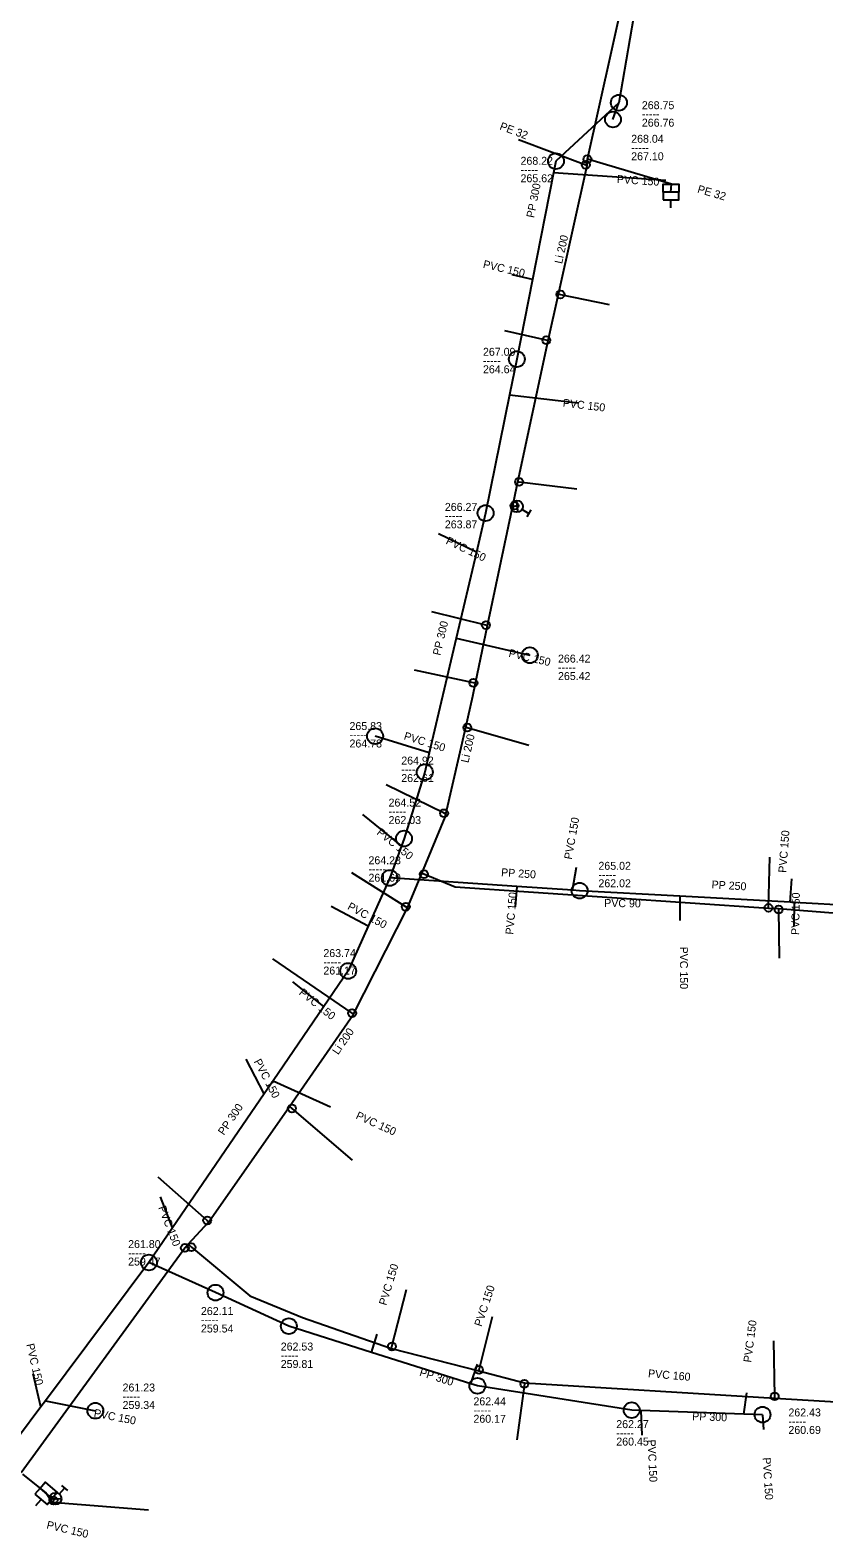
# Model space of a CAD drawing. Extents: x -770828 to -770111, y -1050344 to -1049447.
# Drawn here: x -770589.8 to -770489.8, y -1049915.1 to -1049725.3 of the extents above; entities that cross this region are included whole.
import ezdxf

# ---------------------------------------------------------------- set-up
doc = ezdxf.new("R2010")
doc.units = 0
doc.layers.add('Level 0', color=7, linetype='Continuous')

msp = doc.modelspace()

# ---------------------------------------------------------------- linework, layer by layer
at = {"layer": 'Level 0'}
for p, q in [((-770519.6, -1049741.56), (-770510.08, -1049699.01)), ((-770510.55, -1049704.66), (-770515.63, -1049734.44)), ((-770515.63, -1049734.44), (-770523.56, -1049741.79)), ((-770516.38, -1049736.55), (-770515.63, -1049734.44)), ((-770528.28, -1049739.05), (-770519.81, -1049742.26)), ((-770523.56, -1049741.79), (-770523.85, -1049743.26)), ((-770519.61, -1049742.33), (-770519.6, -1049741.56)), ((-770509, -1049744.7), (-770519.6, -1049741.56)), ((-770523.85, -1049743.26), (-770526.51, -1049756.71)), ((-770509.71, -1049744.21), (-770523.85, -1049743.26)), ((-770523.22, -1049758.53), (-770519.61, -1049742.33)), ((-770519.81, -1049742.26), (-770519.61, -1049742.33)), ((-770509.07, -1049745.68), (-770509, -1049744.7)), ((-770509.07, -1049747.68), (-770509.07, -1049746.68)), ((-770526.51, -1049756.71), (-770529.08, -1049756.12)), ((-770526.51, -1049756.71), (-770528.49, -1049766.72)), ((-770524.53, -1049764.39), (-770523.22, -1049758.53)), ((-770523.22, -1049758.53), (-770522.99, -1049758.58)), ((-770522.99, -1049758.58), (-770516.85, -1049759.86)), ((-770524.77, -1049764.34), (-770530.01, -1049763.18)), ((-770528.36, -1049782.17), (-770524.53, -1049764.39)), ((-770524.53, -1049764.39), (-770524.77, -1049764.34)), ((-770528.49, -1049766.72), (-770529.4, -1049771.21)), ((-770529.4, -1049771.21), (-770532.42, -1049786.11)), ((-770529.4, -1049771.21), (-770520.78, -1049772.23)), ((-770529.09, -1049785.56), (-770528.36, -1049782.17)), ((-770528.36, -1049782.17), (-770528.2, -1049782.19)), ((-770528.2, -1049782.19), (-770520.92, -1049783.05)), ((-770532.17, -1049800.26), (-770529.09, -1049785.56)), ((-770529.09, -1049785.56), (-770528.78, -1049785.17)), ((-770528.78, -1049785.17), (-770528.48, -1049785.26)), ((-770528.59, -1049784.52), (-770528.37, -1049786)), ((-770532.42, -1049786.11), (-770533.57, -1049791.01)), ((-770527.83, -1049785.64), (-770526.96, -1049786.14)), ((-770526.71, -1049785.7), (-770527.21, -1049786.57)), ((-770533.57, -1049791.01), (-770538.35, -1049788.72)), ((-770533.57, -1049791.01), (-770536.12, -1049801.86)), ((-770532.38, -1049800.21), (-770539.18, -1049798.56)), ((-770533.7, -1049807.54), (-770532.17, -1049800.26)), ((-770532.17, -1049800.26), (-770532.38, -1049800.21)), ((-770536.12, -1049801.86), (-770539.51, -1049816.3)), ((-770536.12, -1049801.86), (-770526.85, -1049804.01)), ((-770533.95, -1049807.49), (-770541.38, -1049805.89)), ((-770534.04, -1049809.17), (-770533.7, -1049807.54)), ((-770533.7, -1049807.54), (-770533.95, -1049807.49)), ((-770534.92, -1049813.05), (-770534.04, -1049809.17)), ((-770537.41, -1049824.03), (-770534.92, -1049813.05)), ((-770534.92, -1049813.05), (-770534.72, -1049813.11)), ((-770534.72, -1049813.11), (-770526.96, -1049815.33)), ((-770539.51, -1049816.3), (-770546.34, -1049814.19)), ((-770539.51, -1049816.3), (-770540.08, -1049818.73)), ((-770540.08, -1049818.73), (-770542.69, -1049827.09)), ((-770537.65, -1049823.91), (-770544.94, -1049820.31)), ((-770543.02, -1049828), (-770547.89, -1049824.08)), ((-770540.44, -1049831.47), (-770537.5, -1049824.41)), ((-770537.41, -1049824.03), (-770537.65, -1049823.91)), ((-770537.5, -1049824.41), (-770537.41, -1049824.03)), ((-770542.69, -1049827.09), (-770543.02, -1049828)), ((-770543.02, -1049828), (-770544.48, -1049832.05)), ((-770521.48, -1049833.59), (-770520.96, -1049830.68)), ((-770496.79, -1049835.81), (-770496.62, -1049829.45)), ((-770542.47, -1049835.67), (-770549.25, -1049831.4)), ((-770544.48, -1049832.05), (-770547.21, -1049838.14)), ((-770528.5, -1049833.12), (-770544.48, -1049832.05)), ((-770542.24, -1049835.81), (-770540.44, -1049831.47)), ((-770540.19, -1049831.57), (-770540.44, -1049831.47)), ((-770536.25, -1049833.19), (-770540.19, -1049831.57)), ((-770494.06, -1049835.1), (-770493.83, -1049832.15)), ((-770496.79, -1049835.91), (-770536.25, -1049833.19)), ((-770528.5, -1049833.12), (-770528.71, -1049835.7)), ((-770521.48, -1049833.59), (-770528.5, -1049833.12)), ((-770520.58, -1049833.65), (-770521.48, -1049833.59)), ((-770507.95, -1049834.34), (-770520.58, -1049833.65)), ((-770494.06, -1049835.1), (-770507.95, -1049834.34)), ((-770507.95, -1049834.34), (-770507.94, -1049837.4)), ((-770547.21, -1049838.14), (-770551.85, -1049835.65)), ((-770549.05, -1049849.2), (-770542.24, -1049835.81)), ((-770542.24, -1049835.81), (-770542.47, -1049835.67)), ((-770496.79, -1049835.91), (-770496.79, -1049835.81)), ((-770495.51, -1049835.93), (-770496.79, -1049835.91)), ((-770495.51, -1049835.93), (-770495.51, -1049836.03)), ((-770484.64, -1049836.81), (-770495.51, -1049835.93)), ((-770495.51, -1049836.03), (-770495.45, -1049842.17)), ((-770493.55, -1049835.13), (-770494.06, -1049835.1)), ((-770493.55, -1049835.13), (-770493.6, -1049838.11)), ((-770486.03, -1049835.55), (-770493.55, -1049835.13)), ((-770547.21, -1049838.14), (-770549.73, -1049843.76)), ((-770549.24, -1049849.07), (-770559.22, -1049842.22)), ((-770549.73, -1049843.76), (-770552.8, -1049848.25)), ((-770552.8, -1049848.25), (-770556.7, -1049845.13)), ((-770552.8, -1049848.25), (-770559.19, -1049857.6)), ((-770557.11, -1049860.82), (-770549.05, -1049849.2)), ((-770549.05, -1049849.2), (-770549.24, -1049849.07)), ((-770560.31, -1049859.24), (-770562.59, -1049854.87)), ((-770559.19, -1049857.6), (-770560.31, -1049859.24)), ((-770559.19, -1049857.6), (-770551.94, -1049860.87)), ((-770560.31, -1049859.24), (-770571.84, -1049876.11)), ((-770567.28, -1049875.34), (-770557.11, -1049860.82)), ((-770557.11, -1049860.82), (-770556.81, -1049861.07)), ((-770556.81, -1049861.07), (-770549.23, -1049867.58)), ((-770567.48, -1049875.17), (-770573.64, -1049869.74)), ((-770571.84, -1049876.11), (-770573.37, -1049872.19)), ((-770571.84, -1049876.11), (-770574.82, -1049880.47)), ((-770569.87, -1049878.17), (-770567.28, -1049875.34)), ((-770567.28, -1049875.34), (-770567.48, -1049875.17)), ((-770590.92, -1049906.89), (-770570.29, -1049878.63)), ((-770570.29, -1049878.63), (-770569.87, -1049878.17)), ((-770569.87, -1049878.17), (-770569.47, -1049878.55)), ((-770569.47, -1049878.55), (-770562.12, -1049884.66)), ((-770574.82, -1049880.47), (-770587.86, -1049897.9)), ((-770566.44, -1049884.26), (-770574.82, -1049880.47)), ((-770557.2, -1049888.48), (-770566.44, -1049884.26)), ((-770544.21, -1049891.04), (-770542.38, -1049883.87)), ((-770562.12, -1049884.66), (-770555.49, -1049887.4)), ((-770555.49, -1049887.4), (-770544.27, -1049891.28)), ((-770533.25, -1049894), (-770531.56, -1049887.28)), ((-770546.78, -1049891.78), (-770557.2, -1049888.48)), ((-770546.78, -1049891.78), (-770546.09, -1049889.5)), ((-770534.27, -1049895.74), (-770546.78, -1049891.78)), ((-770544.27, -1049891.28), (-770544.21, -1049891.04)), ((-770544.27, -1049891.28), (-770533.28, -1049894.12)), ((-770496.01, -1049897.32), (-770496.13, -1049890.33)), ((-770534.27, -1049895.74), (-770533.44, -1049893.26)), ((-770588.42, -1049898.65), (-770589.39, -1049894.48)), ((-770533.28, -1049894.12), (-770533.25, -1049894)), ((-770533.28, -1049894.12), (-770527.52, -1049895.6)), ((-770527.52, -1049895.6), (-770527.54, -1049895.76)), ((-770527.52, -1049895.6), (-770496.01, -1049897.54)), ((-770533.45, -1049896), (-770534.27, -1049895.74)), ((-770514.02, -1049899.06), (-770533.45, -1049896)), ((-770527.54, -1049895.76), (-770528.48, -1049902.8)), ((-770499.88, -1049899.55), (-770499.53, -1049896.87)), ((-770496.01, -1049897.54), (-770496.01, -1049897.32)), ((-770496.01, -1049897.54), (-770485.03, -1049898.21)), ((-770588.42, -1049898.65), (-770598, -1049911.45)), ((-770587.86, -1049897.9), (-770588.42, -1049898.65)), ((-770587.86, -1049897.9), (-770581.57, -1049899.13)), ((-770512.87, -1049899.1), (-770514.02, -1049899.06)), ((-770499.88, -1049899.55), (-770512.87, -1049899.1)), ((-770512.87, -1049899.1), (-770512.73, -1049902.22)), ((-770497.55, -1049899.63), (-770499.88, -1049899.55)), ((-770497.55, -1049899.63), (-770497.43, -1049901.5)), ((-770590.76, -1049907.11), (-770587.77, -1049909.53)), ((-770586.11, -1049909.64), (-770585.47, -1049908.87)), ((-770585.85, -1049908.55), (-770585.08, -1049909.19)), ((-770589.06, -1049911.06), (-770588.41, -1049910.3)), ((-770587.77, -1049909.53), (-770587.01, -1049910.63)), ((-770587.34, -1049910.19), (-770585.84, -1049910.24)), ((-770587.01, -1049910.63), (-770586.85, -1049910.42)), ((-770587.01, -1049910.63), (-770574.88, -1049911.6)), ((-770586.85, -1049910.42), (-770586.59, -1049910.21))]:
    msp.add_line(p, q, dxfattribs=at)
for points in [[(-770510.07, -1049745.68), (-770510.07, -1049744.68), (-770508.07, -1049744.68), (-770508.07, -1049745.68)], [(-770588.54, -1049908.89), (-770587.89, -1049908.12), (-770586.36, -1049909.41), (-770587, -1049910.17)]]:
    msp.add_lwpolyline(points, dxfattribs=at)
for points in [[(-770510.07, -1049746.68), (-770508.07, -1049746.68), (-770508.07, -1049745.68), (-770510.07, -1049745.68)], [(-770589.18, -1049909.65), (-770587.65, -1049910.94), (-770587, -1049910.17), (-770588.54, -1049908.89)]]:
    msp.add_lwpolyline(points, close=True, dxfattribs=at)
for centre, radius in [((-770515.63, -1049734.44), 1), ((-770516.38, -1049736.55), 1), ((-770523.56, -1049741.79), 1), ((-770519.81, -1049742.26), 0.5), ((-770519.6, -1049741.56), 0.5), ((-770522.99, -1049758.58), 0.5), ((-770524.77, -1049764.34), 0.5), ((-770528.49, -1049766.72), 1), ((-770528.2, -1049782.19), 0.5), ((-770532.42, -1049786.11), 1), ((-770528.78, -1049785.17), 0.5), ((-770528.48, -1049785.26), 0.75), ((-770532.38, -1049800.21), 0.5), ((-770526.85, -1049804.01), 1), ((-770533.95, -1049807.49), 0.5), ((-770546.34, -1049814.19), 1), ((-770534.72, -1049813.11), 0.5), ((-770540.08, -1049818.73), 1), ((-770537.65, -1049823.91), 0.5), ((-770542.69, -1049827.09), 1), ((-770544.48, -1049832.05), 1), ((-770540.19, -1049831.57), 0.5), ((-770520.58, -1049833.65), 1), ((-770542.47, -1049835.67), 0.5), ((-770496.79, -1049835.81), 0.5), ((-770495.51, -1049836.03), 0.5), ((-770549.73, -1049843.76), 1), ((-770549.24, -1049849.07), 0.5), ((-770556.81, -1049861.07), 0.5), ((-770567.48, -1049875.17), 0.5), ((-770570.29, -1049878.63), 0.5), ((-770569.47, -1049878.55), 0.5), ((-770574.82, -1049880.47), 1), ((-770566.44, -1049884.26), 1), ((-770557.2, -1049888.48), 1), ((-770544.21, -1049891.04), 0.5), ((-770533.25, -1049894), 0.5), ((-770533.45, -1049896), 1), ((-770527.54, -1049895.76), 0.5), ((-770496.01, -1049897.32), 0.5), ((-770581.57, -1049899.13), 1), ((-770514.02, -1049899.06), 1), ((-770497.55, -1049899.63), 1), ((-770586.85, -1049910.42), 0.5), ((-770586.59, -1049910.21), 0.75)]:
    msp.add_circle(centre, radius, dxfattribs=at)

# ---------------------------------------------------------------- texts
for s, p in [('268.75', (-770512.74, -1049735.25)), ('-----', (-770512.74, -1049736.35)), ('266.76', (-770512.74, -1049737.45)), ('268.04', (-770514.08, -1049739.48)), ('268.22', (-770528.02, -1049742.25)), ('-----', (-770514.08, -1049740.58)), ('267.10', (-770514.08, -1049741.68)), ('-----', (-770528.02, -1049743.35)), ('265.62', (-770528.02, -1049744.45)), ('267.09', (-770532.75, -1049766.3)), ('-----', (-770532.75, -1049767.4)), ('264.64', (-770532.75, -1049768.5)), ('266.27', (-770537.55, -1049785.83)), ('-----', (-770537.55, -1049786.93)), ('263.87', (-770537.55, -1049788.03)), ('266.42', (-770523.3, -1049804.93)), ('-----', (-770523.3, -1049806.03)), ('265.42', (-770523.3, -1049807.13)), ('-----', (-770549.56, -1049814.52)), ('265.83', (-770549.56, -1049813.42)), ('264.78', (-770549.56, -1049815.62)), ('264.92', (-770543.04, -1049817.77)), ('-----', (-770543.04, -1049818.87)), ('262.61', (-770543.04, -1049819.97)), ('264.52', (-770544.64, -1049823.06)), ('-----', (-770544.64, -1049824.16)), ('262.03', (-770544.64, -1049825.26)), ('-----', (-770547.17, -1049831.42)), ('264.23', (-770547.17, -1049830.32)), ('265.02', (-770518.21, -1049831.02)), ('261.69', (-770547.17, -1049832.52)), ('-----', (-770518.21, -1049832.12)), ('262.02', (-770518.21, -1049833.22)), ('263.74', (-770552.85, -1049842.01)), ('-----', (-770552.85, -1049843.11)), ('261.17', (-770552.85, -1049844.21)), ('261.80', (-770577.44, -1049878.65)), ('-----', (-770577.44, -1049879.75)), ('259.47', (-770577.44, -1049880.85)), ('262.11', (-770568.27, -1049887.08)), ('-----', (-770568.27, -1049888.18)), ('259.54', (-770568.27, -1049889.28)), ('262.53', (-770558.22, -1049891.55)), ('-----', (-770558.22, -1049892.65)), ('259.81', (-770558.22, -1049893.75)), ('261.23', (-770578.14, -1049896.71)), ('-----', (-770578.14, -1049897.81)), ('262.44', (-770533.95, -1049898.45)), ('259.34', (-770578.14, -1049898.91)), ('-----', (-770533.95, -1049899.55)), ('262.43', (-770494.28, -1049899.85)), ('260.17', (-770533.95, -1049900.65)), ('262.27', (-770515.96, -1049901.32)), ('-----', (-770494.28, -1049900.95)), ('260.69', (-770494.28, -1049902.05)), ('-----', (-770515.96, -1049902.42)), ('260.45', (-770515.96, -1049903.52))]:
    msp.add_text(s, height=1, dxfattribs=at).set_placement(p)
for s, rotation, p in [('PE 32', 339.244, (-770530.73, -1049737.78)), ('PVC 150', 356.156, (-770515.91, -1049744.54)), ('PP 300', 78.813, (-770526.32, -1049748.99)), ('PE 32', 343.499, (-770505.82, -1049745.73)), ('Li 200', 77.437, (-770522.79, -1049754.78)), ('PVC 150', 347.071, (-770532.81, -1049755.21)), ('PVC 150', 353.252, (-770522.73, -1049772.7)), ('PVC 150', 334.402, (-770537.51, -1049789.93)), ('PP 300', 76.788, (-770538.12, -1049804.1)), ('PVC 150', 346.942, (-770529.58, -1049804.18)), ('PVC 150', 342.832, (-770542.79, -1049814.59)), ('Li 200', 77.221, (-770534.58, -1049817.62)), ('PVC 150', 79.869, (-770521.56, -1049829.78)), ('PVC 150', 321.168, (-770546.21, -1049826.48)), ('PVC 150', 85.542, (-770494.56, -1049831.43)), ('PP 250', 356.17, (-770530.49, -1049831.82)), ('PP 250', 356.634, (-770503.98, -1049833.36)), ('PVC 150', 85.347, (-770528.93, -1049839.21)), ('PVC 90', 359.105, (-770517.49, -1049835.69)), ('PVC 150', 89.039, (-770492.93, -1049839.24)), ('PVC 150', 331.78, (-770549.91, -1049835.94)), ('PVC 150', 270.187, (-770507.95, -1049840.7)), ('PVC 150', 321.34, (-770556.01, -1049846.65)), ('Li 200', 55.254, (-770551, -1049854.38)), ('PVC 150', 297.553, (-770561.64, -1049855.15)), ('PP 300', 55.67, (-770565.38, -1049864.52)), ('PVC 150', 335.723, (-770548.85, -1049862.32)), ('PVC 150', 291.321, (-770573.67, -1049873.55)), ('PVC 150', 73.163, (-770544.93, -1049885.94)), ('PVC 150', 71.496, (-770532.93, -1049888.61)), ('PVC 150', 82.559, (-770498.97, -1049893.1)), ('PVC 150', 283.095, (-770590.28, -1049890.79)), ('PP 300', 342.435, (-770540.83, -1049894.71)), ('PVC 160', 355.035, (-770511.99, -1049894.91)), ('PVC 150', 348.936, (-770581.82, -1049899.87)), ('PP 300', 358.016, (-770506.41, -1049900.32)), ('PVC 150', 272.569, (-770512.02, -1049902.79)), ('PVC 150', 273.672, (-770497.53, -1049905.05)), ('PVC 150', 346.783, (-770587.78, -1049913.95))]:
    msp.add_text(s, height=1, rotation=rotation, dxfattribs=at).set_placement(p)

doc.saveas('drawing.dxf')
